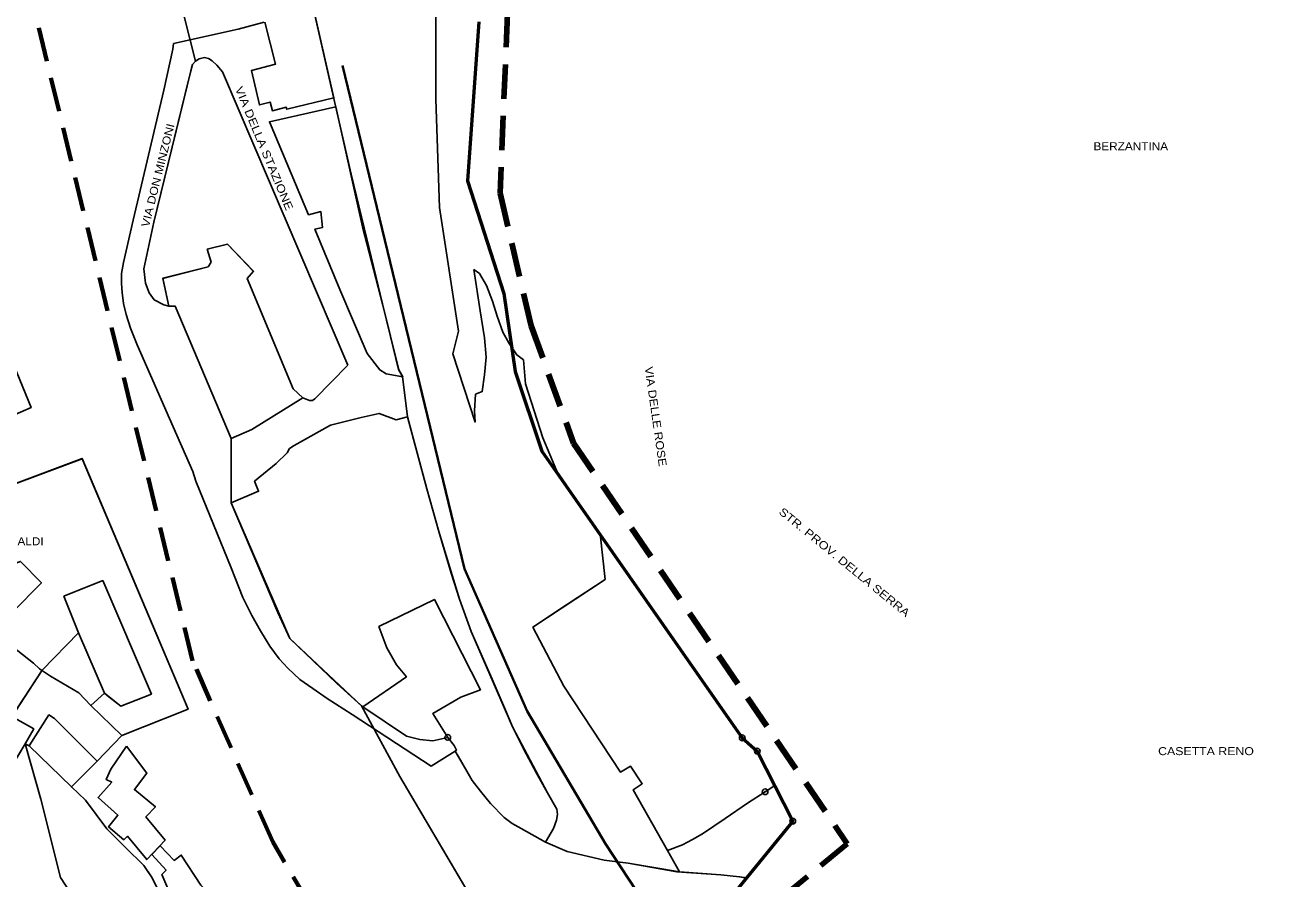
# Model space of a CAD drawing. Extents: x 654952 to 658955, y 890426 to 894481.
# Drawn here: x 658161.5 to 658599.2, y 890943.2 to 891242 of the extents above; entities that cross this region are included whole.
import ezdxf

# ---------------------------------------------------------------- set-up
doc = ezdxf.new("R2010")
doc.units = 0
doc.header["$LTSCALE"] = 4
doc.header["$PDMODE"] = 32
doc.header["$PDSIZE"] = 2
doc.linetypes.add('MEDIUM_DASHED', pattern=[4.5, 3, -1.5])
for name, color, linetype, lineweight in [('1', 7, 'Continuous', 25), ('14', 7, 'Continuous', 25), ('16', 7, 'Continuous', 25), ('18', 7, 'Continuous', 25), ('35', 7, 'Continuous', 25), ('4', 7, 'Continuous', 25), ('45', 7, 'Continuous', 25), ('55', 7, 'Continuous', 25), ('59', 7, 'Continuous', 53), ('6', 7, 'Continuous', 25), ('7', 7, 'MEDIUM_DASHED', 100), ('9', 7, 'Continuous', 25)]:
    doc.layers.add(name, color=color, linetype=linetype, lineweight=lineweight)
doc.layers.add('58', color=7, linetype='Continuous')

msp = doc.modelspace()

# ---------------------------------------------------------------- linework, layer by layer
at = {"layer": '1'}
for points in [[(658220.26, 891085.74), (658212.1, 891104.32), (658205.38, 891119.55), (658200.77, 891130.13), (658198.42, 891135.98), (658196.86, 891140.75), (658196, 891144.56), (658195.48, 891148.38), (658195.28, 891151.61), (658195.3, 891155.07), (658195.9, 891158.92), (658199.36, 891173.77), (658210.01, 891219.26), (658213.27, 891233.58), (658213.47, 891235.51), (658236.11, 891240.63), (658245.2, 891242.97)], [(658119.5, 891157.43), (658112.67, 891144.83), (658114.68, 891148.52), (658112.44, 891144.52), (658126.27, 891135.91), (658122.7, 891129.79), (658117.35, 891120.99), (658106.99, 891103.92), (658115.39, 891089.52), (658116.4, 891087.79), (658121.89, 891091.2), (658128.73, 891081.42), (658134.47, 891072.67), (658181.52, 891090.26), (658218.54, 891002.58), (658195.38, 890993.42), (658184.51, 891003.86), (658180.37, 891008.29), (658170.47, 891014.21), (658166.6, 891016.69), (658164.47, 891018.68), (658153.51, 891027.33), (658145.94, 891016.68), (658139.53, 891006.49)], [(658170.47, 891014.21), (658180.37, 891008.29), (658184.51, 891003.86), (658195.38, 890993.42), (658218.54, 891002.58), (658181.48, 891090.36), (658134.43, 891072.77)], [(658335.11, 890960.84), (658331.98, 890962.56), (658329.16, 890964.7), (658324.37, 890969.61), (658320.87, 890973.96), (658317.98, 890977.66), (658316.1, 890980.92), (658311.96, 890987.97), (658303.59, 890982.72), (658275.92, 891000.76), (658267.26, 891006.39), (658262.22, 891009.86), (658257.62, 891012.96), (658253.47, 891016.96), (658250.44, 891020.24), (658247.17, 891024.64), (658243.86, 891029.97), (658240.87, 891035.4), (658237.71, 891041.64), (658233.62, 891052.09), (658221.3, 891082.44), (658220.26, 891085.74)], [(658153.51, 891027.33), (658164.47, 891018.68), (658166.6, 891016.69), (658170.47, 891014.21)], [(658144.37, 890983.94), (658154.14, 890977.98), (658161.52, 890990.5), (658162.91, 890989.74), (658177.71, 890975.4), (658182.65, 890970.82), (658190.16, 890960.7), (658196.63, 890954.23), (658203.08, 890947.87), (658204.42, 890945.86), (658205.72, 890943.95), (658214.64, 890926.33)], [(658404.44, 890930.41), (658406.91, 890934.75), (658414.05, 890943.51), (658411.52, 890943.99), (658404.98, 890944.67), (658389.6, 890945.68), (658372.54, 890948.71), (658364.14, 890949.78), (658351.24, 890952.81), (658343.66, 890956.03), (658335.11, 890960.84)]]:
    msp.add_lwpolyline(points, dxfattribs=at)
msp.add_lwpolyline([(658188.7, 891047.62), (658205.74, 891007.88), (658195, 891003.64), (658189.34, 891008.18), (658184.51, 891003.86), (658195.38, 890993.42), (658186.69, 890984.36), (658177.71, 890975.4), (658162.91, 890989.74), (658161.52, 890990.5), (658154.14, 890977.98), (658144.37, 890983.94), (658152.75, 890997.52), (658154.72, 890996.26), (658156.93, 891000.08), (658167.45, 891016.27), (658180.17, 891029.32), (658175.08, 891042.1)], close=True, dxfattribs=at)
at = {"layer": '14'}
for points in [[(658430.14, 890963.41), (658423.88, 890975.93), (658420.44, 890973.7), (658414.28, 890969.74), (658406.43, 890964.35), (658398.57, 890958.97), (658395.04, 890957.06), (658391.5, 890955.16), (658386.36, 890953.14)], [(658386.36, 890953.14), (658390.5, 890945.64), (658404.98, 890944.67), (658411.52, 890943.99), (658414.01, 890943.61), (658430.14, 890963.41)]]:
    msp.add_lwpolyline(points, dxfattribs=at)
msp.add_point((658430.14, 890963.41), dxfattribs=at)
at = {"layer": '16'}
msp.add_lwpolyline([(658279.68, 891003.45), (658294.94, 891013.98), (658291.53, 891018.15), (658288.11, 891024.03), (658285.35, 891031.54), (658304.72, 891041.04), (658320.88, 891009.43), (658314.04, 891006.84), (658304.15, 891001.09), (658309.4, 890992.75), (658304.15, 890991.53), (658299.7, 890991.96), (658294.99, 890993.22)], close=True, dxfattribs=at)
at = {"layer": '18'}
for points in [[(658281.25, 891127.05), (658271.69, 891149.51), (658262.91, 891170.63), (658265.6, 891171.19), (658265.04, 891176.76), (658260.69, 891175.61), (658247.01, 891208.18), (658270.21, 891213.41), (658279.62, 891171.38), (658286.61, 891144.5), (658292.27, 891121.32), (658293.73, 891118.92), (658287.88, 891120.01), (658285.6, 891121.35)], [(658240.84, 891100.54), (658233.64, 891097.38), (658214.07, 891143.59), (658211.81, 891143.69), (658209.68, 891153.39), (658225.55, 891157.45), (658226.58, 891159.03), (658225.28, 891163.6), (658232.35, 891165.32), (658241.49, 891155.84), (658239.23, 891153.36), (658255.38, 891114.7), (658258.65, 891111.55)]]:
    msp.add_lwpolyline(points, close=True, dxfattribs=at)
at = {"layer": '35'}
for points in [[(658213.99, 890867.74), (658185.33, 890926.17), (658173.89, 890943.74), (658167.04, 890971.14), (658161.52, 890990.5), (658154.14, 890977.98), (658144.37, 890983.94), (658152.75, 890997.52), (658139.53, 891006.49)], [(658177.71, 890975.4), (658162.91, 890989.74), (658161.52, 890990.5)], [(658161.52, 890990.5), (658167.04, 890971.14), (658173.89, 890943.74), (658185.33, 890926.17), (658213.99, 890867.74)], [(658203.08, 890947.87), (658196.63, 890954.23), (658190.16, 890960.7), (658182.65, 890970.82), (658177.71, 890975.4)], [(658223.22, 890912.19), (658218.42, 890919.34), (658214.64, 890926.33), (658205.72, 890943.95), (658204.42, 890945.86), (658203.08, 890947.87)]]:
    msp.add_lwpolyline(points, dxfattribs=at)
msp.add_lwpolyline([(658203.08, 890947.87), (658204.42, 890945.86), (658205.72, 890943.95)], close=True, dxfattribs=at)
at = {"layer": '4'}
for points in [[(658245.36, 891243.07), (658249.11, 891228.29), (658240.77, 891226.17), (658243.51, 891214.08), (658247.24, 891215.06), (658248.07, 891212.05), (658252.92, 891213.24), (658253.09, 891212.58), (658269.5, 891216.54), (658262.5, 891247.22)], [(658152.75, 890997.52), (658154.72, 890996.26), (658156.93, 891000.08), (658164.57, 890995.68), (658161.52, 890990.5), (658161.52, 890990.5), (658158.95, 890986.14)]]:
    msp.add_lwpolyline(points, dxfattribs=at)
for points in [[(658139.9, 891133.78), (658151.14, 891138.38), (658163.6, 891108.18), (658151.49, 891102.96), (658148.28, 891107.46), (658147.53, 891107), (658142.82, 891114.02), (658147.18, 891116.12)], [(658145.28, 891046.64), (658152.46, 891053.12), (658153.29, 891051.96), (658159.94, 891054.32), (658167.25, 891046.8), (658157.21, 891036.62)], [(658175.08, 891042.1), (658180.17, 891029.32), (658189.34, 891008.18), (658190.84, 891006.96), (658195, 891003.64), (658205.74, 891007.88), (658188.7, 891047.62)], [(658162.91, 890989.74), (658169.83, 891000.58), (658171.77, 890999.38), (658186.69, 890984.36), (658177.71, 890975.4)], [(658197.02, 890989.72), (658204.17, 890980.26), (658199.77, 890974.48), (658207.11, 890968.44), (658203.77, 890964.88), (658210.51, 890956.74), (658204.08, 890949.98), (658197.33, 890958.16), (658196.11, 890956.9), (658190.74, 890961.46), (658194.01, 890965.52), (658187.04, 890971.7), (658191.86, 890977.02), (658189.85, 890978.04), (658191.51, 890981.56)]]:
    msp.add_lwpolyline(points, close=True, dxfattribs=at)
at = {"layer": '45'}
for points in [[(658311.24, 891127), (658313.13, 891134.91), (658306.49, 891178.17), (658305.21, 891216.08), (658305.25, 891262.13), (658305.35, 891268.02), (658305.43, 891283.96), (658305.52, 891299.89), (658305.43, 891308.15), (658305.46, 891315.77), (658305.24, 891322.28), (658305.02, 891327.76), (658304.14, 891335.88), (658303.85, 891339.65), (658303.57, 891343.42), (658302.48, 891350.94), (658301.51, 891356.64), (658293.05, 891386.66), (658292.07, 891392.72), (658268.41, 891385.81), (658252.99, 891450.05), (658286.48, 891457.94), (658291.78, 891470.63)], [(658322.2, 890929.02), (658292.7, 890979.09), (658279.21, 891003.76), (658254.12, 891027.36), (658233.63, 891074.77), (658233.64, 891097.38), (658214.07, 891143.59), (658211.81, 891143.68), (658210.05, 891144.12), (658206.63, 891145.87), (658204.96, 891148.26), (658203.71, 891151.67), (658203.11, 891156.69), (658206.56, 891173.02), (658219.51, 891226.01), (658220.1, 891228.19), (658221.11, 891229.42), (658205.78, 891290.15)], [(658261.46, 891251.79), (658268.52, 891220.82), (658275.58, 891189.85), (658281.1, 891167.17), (658286.61, 891144.5)], [(658320.32, 891243.1), (658316.29, 891187.54), (658329.01, 891148.11), (658333.04, 891120.79), (658342.35, 891092.85), (658362.7, 891063.93), (658409.36, 890996.94), (658412.46, 890992.59), (658417.73, 890987.93), (658423.88, 890975.93), (658430.14, 890963.41), (658406.87, 890934.85)], [(658318.5, 891156.43), (658320.72, 891142.02), (658322.23, 891132.6), (658322.86, 891125.78), (658322.32, 891119.65), (658321.46, 891113.76), (658319.15, 891112.84), (658318.83, 891107.01), (658318.95, 891103.1), (658311.24, 891127)], [(658335.92, 891124.82), (658333.53, 891126.61), (658330.86, 891130.54), (658328.69, 891134.6), (658326.7, 891140.15), (658325.02, 891145.34), (658323.01, 891150.85), (658320.51, 891155.03), (658318.5, 891156.43)], [(658286.61, 891144.5), (658289.38, 891132.97), (658292.16, 891121.43), (658293.62, 891119.03), (658295.34, 891104.86)], [(658317.63, 891029.76), (658332.21, 890996.24), (658344.3, 890973.31), (658347.53, 890967.63), (658347.8, 890965.73), (658347.47, 890963.77), (658346.37, 890960.84), (658343.66, 890956.03), (658351.24, 890952.81), (658364.14, 890949.78), (658372.54, 890948.71), (658390.5, 890945.64), (658386.36, 890953.14), (658374.3, 890974.43), (658377.47, 890976.49), (658373.32, 890982.67), (658369.83, 890980.58), (658350, 891010.65), (658339.24, 891031.34), (658351.34, 891039.39), (658364.48, 891048.02), (658362.7, 891063.93), (658347.6, 891085.91), (658342.69, 891097.61), (658336.65, 891116.47), (658335.92, 891124.82)], [(658295.34, 891104.86), (658302.04, 891079.68), (658306.33, 891064.8)], [(658306.33, 891064.8), (658313.49, 891041.08), (658317.63, 891029.76)]]:
    msp.add_lwpolyline(points, dxfattribs=at)
at = {"layer": '45', "linetype": 'MEDIUM_DASHED', "lineweight": 70}
msp.add_lwpolyline([(658467.75, 890621.37), (658447.66, 890651.14), (658324.04, 890835.2), (658279.74, 890902.58), (658248.15, 890956.2), (658220.13, 891019.53), (658157.73, 891276.4)], dxfattribs=at)
at = {"layer": '45', "lineweight": 40}
msp.add_lwpolyline([(658550.65, 890677.3), (658530.62, 890706.98), (658407.33, 890890.55), (658364.65, 890955.46), (658337.25, 891001.97), (658315.22, 891051.75), (658272.64, 891227.84)], dxfattribs=at)
msp.add_lwpolyline([(658550.65, 890677.3), (658530.62, 890706.98), (658407.33, 890890.55), (658364.65, 890955.46), (658337.25, 891001.97), (658315.22, 891051.75), (658272.64, 891227.84)], dxfattribs=at)
at = {"layer": '55'}
for points in [[(658206.56, 891173.02), (658218.69, 891222.69), (658219.51, 891226.01), (658220.1, 891228.19), (658221.11, 891229.42), (658205.78, 891290.15), (658200.81, 891288.95)], [(658308.09, 890952.97), (658292.7, 890979.09), (658279.21, 891003.76), (658273.11, 891009.26), (658270.53, 891011.73), (658254.12, 891027.36), (658249.93, 891036.46), (658233.63, 891074.77), (658233.64, 891097.38), (658214.07, 891143.59), (658211.81, 891143.68), (658210.05, 891144.12), (658206.63, 891145.87), (658204.96, 891148.26), (658203.71, 891151.67), (658203.11, 891156.69), (658206.56, 891173.02)], [(658156.84, 890999.94), (658167.45, 891016.27), (658180.17, 891029.32), (658175.08, 891042.1), (658188.7, 891047.62), (658205.74, 891007.88), (658195, 891003.64), (658189.34, 891008.18), (658184.51, 891003.86), (658195.38, 890993.42), (658186.69, 890984.36), (658177.71, 890975.4), (658177.71, 890975.4), (658162.91, 890989.74), (658161.52, 890990.5), (658167.04, 890971.14), (658173.89, 890943.74), (658185.33, 890926.17)], [(658274.77, 890860.54), (658281.88, 890853.09), (658285.47, 890848.53), (658281.88, 890853.09), (658341.53, 890899.7), (658322.2, 890929.02), (658308.09, 890952.97)]]:
    msp.add_lwpolyline(points, dxfattribs=at)
at = {"layer": '59'}
msp.add_lwpolyline([(658320.32, 891243.1), (658316.29, 891187.54), (658329.01, 891148.11), (658333.04, 891120.79), (658342.35, 891092.85), (658409.36, 890996.94), (658412.46, 890992.59), (658417.73, 890987.93), (658430.14, 890963.41), (658406.88, 890934.85), (658404.4, 890930.51), (658409.86, 890927.97), (658423.01, 890929.57), (658438.83, 890927.71), (658472.34, 890915.29), (658557.03, 890869.66)], dxfattribs=at)
at = {"layer": '6'}
msp.add_lwpolyline([(658205.87, 890951.78), (658210.83, 890946.27), (658209.42, 890944.8), (658213.96, 890934.17), (658218.02, 890927.98), (658220.79, 890929.13), (658229.43, 890934.5), (658223, 890941.03), (658216.15, 890951.53), (658213.67, 890949.7), (658208.77, 890954.82)], close=True, dxfattribs=at)
at = {"layer": '7'}
msp.add_lwpolyline([(658330.3, 891246.22), (658327.72, 891183.18), (658338.55, 891136.81), (658353.44, 891095.71), (658449.21, 890955.48), (658420.28, 890931.68), (658481.44, 890907.81), (658636.65, 890815.27), (658732.37, 890716.91), (658771.82, 890588.13), (658747.24, 890482.65), (658726.56, 890461.94), (658714.04, 890498.12), (658642.13, 890543.72), (658607.69, 890579.19), (658520.59, 890568.04), (658475.02, 890599.46), (658360.56, 890605.54), (658254.22, 890706.88), (658248.14, 890844.7), (658184.33, 890889.29), (658123.56, 891003.8)], dxfattribs=at)
at = {"layer": '9'}
msp.add_line((658262.92, 891111.23), (658274.4, 891122.96), dxfattribs=at)
for points in [[(658274.4, 891122.96), (658230.62, 891225.68), (658228.67, 891228), (658227.03, 891229.49), (658225.66, 891230.26), (658224.35, 891230.65), (658222.38, 891230.15), (658221.11, 891229.42), (658220.1, 891228.19), (658219.51, 891226.01), (658218.69, 891222.69), (658206.56, 891173.02), (658203.11, 891156.69), (658203.71, 891151.67), (658204.96, 891148.26), (658206.63, 891145.87), (658210.05, 891144.12), (658211.81, 891143.68), (658209.68, 891153.38), (658225.55, 891157.44), (658226.58, 891159.02), (658225.28, 891163.59), (658232.35, 891165.31), (658241.49, 891155.83), (658239.23, 891153.35), (658255.38, 891114.69), (658258.65, 891111.54), (658261.06, 891110.61), (658262.12, 891110.64), (658262.92, 891111.23)], [(658325, 891013.13), (658317.63, 891029.76), (658313.49, 891041.08), (658310.63, 891050.19), (658306.33, 891064.8), (658302.04, 891079.68), (658295.34, 891104.86), (658291.39, 891103.81), (658285.4, 891106.09), (658279.17, 891104.64), (658268.34, 891102.02), (658255.62, 891094.91), (658254.06, 891093.8), (658253.19, 891092.26), (658249.4, 891088.61), (658241.81, 891082.37), (658243.25, 891078.86), (658233.63, 891074.77), (658249.93, 891036.46), (658254.12, 891027.36), (658270.53, 891011.73), (658273.11, 891009.26), (658279.21, 891003.76), (658279.68, 891003.45)], [(658412.46, 890992.59), (658409.36, 890996.94), (658362.7, 891063.93), (658364.48, 891048.02), (658339.24, 891031.34)], [(658279.68, 891003.45), (658294.94, 891013.98), (658291.53, 891018.15), (658288.11, 891024.03), (658285.35, 891031.54), (658304.72, 891041.04), (658320.88, 891009.43), (658314.04, 891006.84), (658304.15, 891001.09), (658309.4, 890992.75)], [(658339.24, 891031.34), (658350, 891010.65), (658369.83, 890980.58), (658373.32, 890982.67), (658377.47, 890976.49), (658374.3, 890974.43), (658386.36, 890953.14), (658391.5, 890955.16), (658395.04, 890957.06), (658398.57, 890958.97), (658406.43, 890964.35), (658414.28, 890969.74), (658420.44, 890973.7)], [(658346.37, 890960.84), (658347.47, 890963.77), (658347.8, 890965.73), (658347.53, 890967.63), (658344.3, 890973.31), (658340.51, 890980.27), (658335.93, 890988.7), (658332.21, 890996.24), (658329.65, 891002.28), (658327.02, 891008.17), (658325, 891013.13)], [(658309.4, 890992.75), (658311.66, 890989.85), (658312.48, 890988.27), (658311.96, 890987.97), (658313, 890986.19)], [(658313, 890986.19), (658316.1, 890980.92), (658317.98, 890977.66), (658320.87, 890973.96), (658324.37, 890969.61), (658329.16, 890964.7), (658331.99, 890962.56), (658335.11, 890960.84), (658343.66, 890956.03), (658346.37, 890960.84)]]:
    msp.add_lwpolyline(points, dxfattribs=at)
for p in [(658309.4, 890992.75), (658412.46, 890992.59), (658417.73, 890987.93), (658420.44, 890973.7)]:
    msp.add_point(p, dxfattribs=at)

# ---------------------------------------------------------------- texts
at = {"layer": '58'}
for s, height, rotation, width, p in [('VIA DELLA STAZIONE', 2.803, 292.706, 1.2, (658234.91, 891219.77)), ('VIA DON MINZONI', 2.802, 75.964, 1.15, (658204.84, 891171.11)), ('VIA DELLE ROSE', 2.802, 278.175, 1.15, (658378.31, 891122.26)), ('STR. PROV. DELLA SERRA', 2.801, 320.716, 1.2, (658424.99, 891071.23))]:
    msp.add_text(s, height=height, rotation=rotation, dxfattribs=dict(at, width=width)).set_placement(p)
for s, width, p in [('BERZANTINA', 1.1, (658535.36, 891198.21)), ('PIAZZA GARIBALDI', 1.1, (658130.47, 891059.95)), ('CASETTA RENO', 1.15, (658557.98, 890986.53))]:
    msp.add_text(s, height=2.801, dxfattribs=dict(at, width=width)).set_placement(p)

doc.saveas('drawing.dxf')
